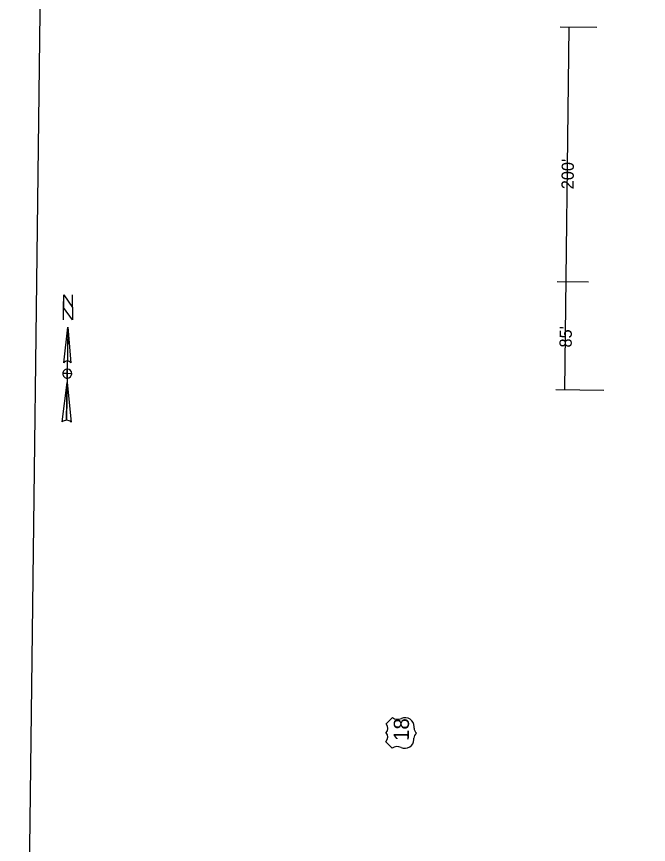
# Model space of a CAD drawing. Extents: x 4959127 to 4960275, y 3872379 to 3884458.
# Drawn here: x 4959219 to 4959716, y 3880719 to 3881370 of the extents above; entities that cross this region are included whole.
import ezdxf

# ---------------------------------------------------------------- set-up
doc = ezdxf.new("R2010")
doc.units = 0
for name, color, linetype in [('Cell', 7, 'Continuous'), ('dsnCellsHighwaySymbols', 7, 'Continuous'), ('NamedBoundary', 7, 'Continuous'), ('SheetText', 7, 'Continuous')]:
    doc.layers.add(name, color=color, linetype=linetype)

msp = doc.modelspace()

# ---------------------------------------------------------------- linework, layer by layer
at = {"layer": 'Cell'}
for p, q in [((4959259.09, 3881126.04), (4959258.19, 3881052.8)), ((4959259.09, 3881126.04), (4959261.56, 3881097.84)), ((4959255.93, 3881097.9), (4959255.93, 3881097.9)), ((4959256.04, 3881098.16), (4959256.57, 3881098.74)), ((4959258.59, 3881085.9), (4959258.59, 3881085.9)), ((4959254.65, 3881051.43), (4959258.55, 3881082.38))]:
    msp.add_line(p, q, dxfattribs=at)
for points in [[(4959255.64, 3881131.72), (4959255.88, 3881151.43), (4959262.8, 3881141.49), (4959262.92, 3881151.35)], [(4959255.93, 3881097.9), (4959259.09, 3881126.04), (4959258.76, 3881099.28)], [(4959258.59, 3881085.9), (4959258.64, 3881089.42), (4959255.12, 3881089.46)], [(4959262.16, 3881089.38), (4959258.64, 3881089.42), (4959258.68, 3881092.94)], [(4959258.19, 3881052.8), (4959258.55, 3881082.38), (4959261.69, 3881051.35)]]:
    msp.add_lwpolyline(points, dxfattribs=at)
msp.add_lwpolyline([(4959262.68, 3881131.63), (4959255.76, 3881141.57), (4959255.88, 3881151.43), (4959262.8, 3881141.49)], close=True, dxfattribs=at)
for centre, radius, start, end in [((4959258.72, 3881095.76), 3.52, 89.31793, 142.42328), ((4959258.72, 3881095.76), 3.52, 36.1456, 89.31938), ((4959258.64, 3881089.42), 3.52, 89.29754, 179.29754), ((4959258.64, 3881089.42), 3.52, 179.29754, 269.29754), ((4959258.64, 3881089.42), 3.52, 269.29754, 359.29754), ((4959258.64, 3881089.42), 3.52, 359.29754, 89.29754), ((4959258.13, 3881047.7), 5.1, 89.28693, 132.91649), ((4959258.13, 3881047.69), 5.11, 45.6996, 89.29819)]:
    msp.add_arc(centre, radius, start, end, dxfattribs=at)
at = {"layer": 'dsnCellsHighwaySymbols'}
for p, q in [((4959514.41, 3880818.97), (4959509.35, 3880814.03)), ((4959531.31, 3880810.76), (4959531.32, 3880811.76)), ((4959531.2, 3880801.77), (4959531.21, 3880802.77)), ((4959509.18, 3880800.04), (4959514.11, 3880794.97))]:
    msp.add_line(p, q, dxfattribs=at)
for centre, radius, start, end in [((4959518.56, 3880824.61), 7, 233.63477, 294.30756), ((4959524.32, 3880811.85), 7, 359.29759, 114.30798), ((4959505.73, 3880810.58), 5, 314.87044, 43.72474), ((4959536.31, 3880810.7), 5, 179.29774, 232.42754), ((4959505.65, 3880803.58), 5, 314.87044, 43.72474), ((4959536.21, 3880802.7), 5, 126.16742, 179.29774), ((4959518.13, 3880789.24), 7, 64.28705, 124.96041), ((4959524.2, 3880801.85), 7, 244.2872, 359.29759)]:
    msp.add_arc(centre, radius, start, end, dxfattribs=at)
at = {"layer": 'NamedBoundary'}
msp.add_lwpolyline([(4959218.82, 3879890.88), (4960218.75, 3879878.62), (4960237.96, 3881446), (4959238.04, 3881458.26)], close=True, dxfattribs=at)
at = {"layer": 'SheetText'}
for p, q in [((4959674.89, 3881361.53), (4959646.28, 3881361.88)), ((4959649.72, 3881076.58), (4959653.21, 3881361.8)), ((4959668.43, 3881161.36), (4959643.83, 3881161.66)), ((4959680.51, 3881076.2), (4959642.78, 3881076.66))]:
    msp.add_line(p, q, dxfattribs=at)

# ---------------------------------------------------------------- texts
at = {"layer": 'dsnCellsHighwaySymbols'}
msp.add_text('18', height=12, rotation=89.29753, dxfattribs=at).set_placement((4959527.18, 3880800.61))
at = {"layer": 'SheetText'}
for s, p in [("200'", (4959656.74, 3881234.35)), ("85'", (4959655.21, 3881109.91))]:
    msp.add_text(s, height=9.6, rotation=89.30425, dxfattribs=at).set_placement(p)

doc.saveas('drawing.dxf')
